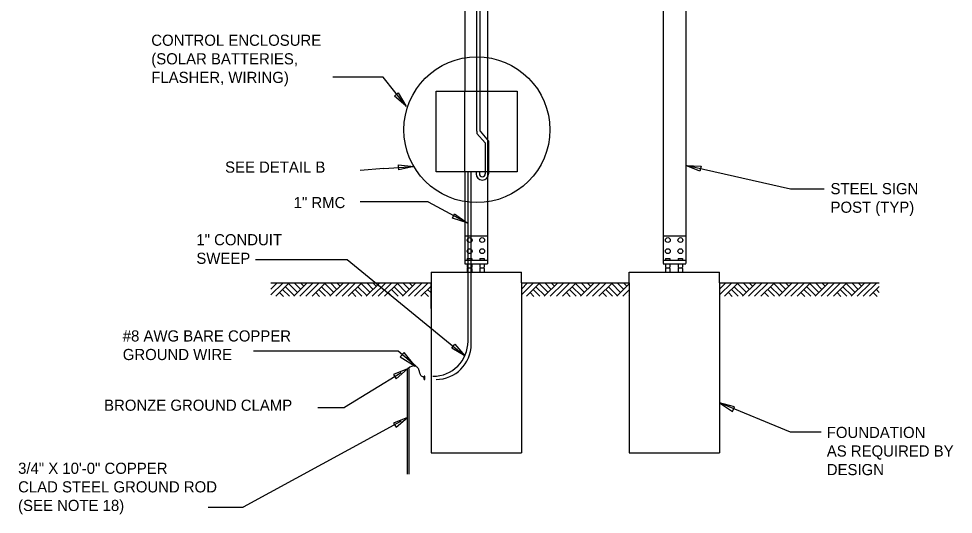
# Model space of a CAD drawing. Extents: x 1299104.6 to 1299141.5, y 239713.3 to 239735.3.
# Drawn here: x 1299119.14 to 1299129.2, y 239723.83 to 239729.17 of the extents above; entities that cross this region are included whole.
import ezdxf

# ---------------------------------------------------------------- set-up
doc = ezdxf.new("R2010")
doc.units = 0
doc.layers.add('DIM TXT', color=7, linetype='Continuous')
doc.layers.add('PTEXT', color=7, linetype='Continuous')

msp = doc.modelspace()

# ---------------------------------------------------------------- linework, layer by layer
at = {"layer": 'DIM TXT'}
for p, q in [((1299123.064, 239728.541), (1299122.522, 239728.541)), ((1299123.314, 239728.224), (1299123.064, 239728.541)), ((1299123.069, 239727.558), (1299122.816, 239727.537)), ((1299123.069, 239727.558), (1299123.392, 239727.579)), ((1299127.446, 239727.334), (1299126.318, 239727.59)), ((1299127.807, 239727.334), (1299127.446, 239727.334)), ((1299123.547, 239727.198), (1299122.816, 239727.198)), ((1299123.547, 239727.198), (1299123.965, 239726.972)), ((1299121.689, 239726.579), (1299122.676, 239726.579)), ((1299122.676, 239726.579), (1299123.941, 239725.54)), ((1299121.854, 239726.196), (1299121.986, 239726.326)), ((1299121.854, 239726.26), (1299121.921, 239726.326)), ((1299121.909, 239726.183), (1299122.053, 239726.326)), ((1299122.1, 239726.182), (1299122.246, 239726.326)), ((1299122.106, 239726.326), (1299122.176, 239726.256)), ((1299122.165, 239726.182), (1299122.311, 239726.326)), ((1299122.174, 239726.326), (1299122.21, 239726.29)), ((1299122.23, 239726.182), (1299122.376, 239726.326)), ((1299122.298, 239726.183), (1299122.443, 239726.326)), ((1299122.49, 239726.182), (1299122.636, 239726.326)), ((1299122.496, 239726.326), (1299122.566, 239726.256)), ((1299122.555, 239726.182), (1299122.701, 239726.326)), ((1299122.563, 239726.326), (1299122.599, 239726.29)), ((1299122.62, 239726.182), (1299122.766, 239726.326)), ((1299122.688, 239726.183), (1299122.833, 239726.326)), ((1299122.88, 239726.182), (1299123.026, 239726.326)), ((1299122.886, 239726.326), (1299122.955, 239726.256)), ((1299122.945, 239726.182), (1299123.091, 239726.326)), ((1299122.953, 239726.326), (1299122.989, 239726.29)), ((1299123.01, 239726.182), (1299123.156, 239726.326)), ((1299123.078, 239726.183), (1299123.223, 239726.326)), ((1299123.27, 239726.182), (1299123.416, 239726.326)), ((1299123.276, 239726.326), (1299123.345, 239726.256)), ((1299123.335, 239726.182), (1299123.481, 239726.326)), ((1299123.343, 239726.326), (1299123.379, 239726.29)), ((1299123.4, 239726.182), (1299123.546, 239726.326)), ((1299124.55, 239726.196), (1299124.682, 239726.326)), ((1299124.55, 239726.26), (1299124.617, 239726.326)), ((1299124.604, 239726.183), (1299124.749, 239726.326)), ((1299124.796, 239726.182), (1299124.942, 239726.326)), ((1299124.802, 239726.326), (1299124.871, 239726.256)), ((1299124.861, 239726.182), (1299125.007, 239726.326)), ((1299124.869, 239726.326), (1299124.905, 239726.29)), ((1299124.926, 239726.182), (1299125.072, 239726.326)), ((1299124.994, 239726.183), (1299125.139, 239726.326)), ((1299125.186, 239726.182), (1299125.332, 239726.326)), ((1299125.192, 239726.326), (1299125.261, 239726.256)), ((1299125.251, 239726.182), (1299125.397, 239726.326)), ((1299125.259, 239726.326), (1299125.295, 239726.29)), ((1299125.316, 239726.182), (1299125.462, 239726.326)), ((1299125.384, 239726.183), (1299125.529, 239726.326)), ((1299125.582, 239726.326), (1299125.651, 239726.256)), ((1299125.649, 239726.326), (1299125.685, 239726.29)), ((1299126.683, 239726.196), (1299126.815, 239726.326)), ((1299126.683, 239726.26), (1299126.75, 239726.326)), ((1299126.737, 239726.183), (1299126.882, 239726.326)), ((1299126.929, 239726.182), (1299127.075, 239726.326)), ((1299126.935, 239726.326), (1299127.005, 239726.256)), ((1299126.994, 239726.182), (1299127.14, 239726.326)), ((1299127.002, 239726.326), (1299127.038, 239726.29)), ((1299127.059, 239726.182), (1299127.205, 239726.326)), ((1299127.127, 239726.183), (1299127.272, 239726.326)), ((1299127.319, 239726.182), (1299127.465, 239726.326)), ((1299127.325, 239726.326), (1299127.394, 239726.256)), ((1299127.384, 239726.182), (1299127.53, 239726.326)), ((1299127.392, 239726.326), (1299127.428, 239726.29)), ((1299127.449, 239726.182), (1299127.595, 239726.326)), ((1299127.517, 239726.183), (1299127.662, 239726.326)), ((1299127.709, 239726.182), (1299127.855, 239726.326)), ((1299127.715, 239726.326), (1299127.784, 239726.256)), ((1299127.774, 239726.182), (1299127.92, 239726.326)), ((1299127.782, 239726.326), (1299127.818, 239726.29)), ((1299127.839, 239726.182), (1299127.985, 239726.326)), ((1299127.907, 239726.183), (1299128.052, 239726.326)), ((1299128.099, 239726.182), (1299128.245, 239726.326)), ((1299128.105, 239726.326), (1299128.174, 239726.256)), ((1299128.164, 239726.182), (1299128.31, 239726.326)), ((1299128.172, 239726.326), (1299128.208, 239726.29)), ((1299128.228, 239726.182), (1299128.375, 239726.326)), ((1299121.981, 239726.255), (1299122.054, 239726.182)), ((1299122.011, 239726.285), (1299122.107, 239726.189)), ((1299122.046, 239726.32), (1299122.142, 239726.223)), ((1299122.371, 239726.255), (1299122.444, 239726.182)), ((1299122.401, 239726.285), (1299122.497, 239726.189)), ((1299122.436, 239726.32), (1299122.532, 239726.223)), ((1299122.761, 239726.255), (1299122.834, 239726.182)), ((1299122.791, 239726.285), (1299122.887, 239726.189)), ((1299122.826, 239726.32), (1299122.922, 239726.223)), ((1299123.151, 239726.255), (1299123.224, 239726.182)), ((1299123.181, 239726.285), (1299123.276, 239726.189)), ((1299123.216, 239726.32), (1299123.312, 239726.223)), ((1299123.468, 239726.183), (1299123.578, 239726.292)), ((1299123.541, 239726.255), (1299123.578, 239726.218)), ((1299123.571, 239726.285), (1299123.578, 239726.278)), ((1299124.677, 239726.255), (1299124.75, 239726.182)), ((1299124.707, 239726.285), (1299124.803, 239726.189)), ((1299124.742, 239726.32), (1299124.838, 239726.223)), ((1299125.067, 239726.255), (1299125.14, 239726.182)), ((1299125.097, 239726.285), (1299125.192, 239726.189)), ((1299125.132, 239726.32), (1299125.228, 239726.223)), ((1299125.457, 239726.255), (1299125.53, 239726.182)), ((1299125.487, 239726.285), (1299125.582, 239726.189)), ((1299125.522, 239726.32), (1299125.618, 239726.223)), ((1299125.576, 239726.182), (1299125.711, 239726.316)), ((1299125.641, 239726.182), (1299125.711, 239726.251)), ((1299126.81, 239726.255), (1299126.883, 239726.182)), ((1299126.84, 239726.285), (1299126.936, 239726.189)), ((1299126.875, 239726.32), (1299126.971, 239726.223)), ((1299127.2, 239726.255), (1299127.273, 239726.182)), ((1299127.23, 239726.285), (1299127.326, 239726.189)), ((1299127.265, 239726.32), (1299127.361, 239726.223)), ((1299127.59, 239726.255), (1299127.663, 239726.182)), ((1299127.62, 239726.285), (1299127.715, 239726.189)), ((1299127.655, 239726.32), (1299127.751, 239726.223)), ((1299127.98, 239726.255), (1299128.052, 239726.182)), ((1299128.01, 239726.285), (1299128.105, 239726.189)), ((1299128.045, 239726.32), (1299128.141, 239726.223)), ((1299128.297, 239726.183), (1299128.401, 239726.286)), ((1299128.37, 239726.255), (1299128.401, 239726.224)), ((1299121.948, 239726.222), (1299121.989, 239726.18)), ((1299122.338, 239726.222), (1299122.379, 239726.18)), ((1299122.728, 239726.222), (1299122.769, 239726.18)), ((1299123.118, 239726.222), (1299123.159, 239726.18)), ((1299123.507, 239726.222), (1299123.549, 239726.18)), ((1299124.644, 239726.222), (1299124.685, 239726.18)), ((1299125.034, 239726.222), (1299125.075, 239726.18)), ((1299125.424, 239726.222), (1299125.465, 239726.18)), ((1299125.706, 239726.182), (1299125.711, 239726.187)), ((1299126.777, 239726.222), (1299126.818, 239726.18)), ((1299127.167, 239726.222), (1299127.208, 239726.18)), ((1299127.557, 239726.222), (1299127.598, 239726.18)), ((1299127.947, 239726.222), (1299127.988, 239726.18)), ((1299128.336, 239726.222), (1299128.378, 239726.18)), ((1299123.225, 239725.592), (1299121.666, 239725.592)), ((1299123.414, 239725.429), (1299123.225, 239725.592)), ((1299123.257, 239725.357), (1299122.648, 239724.986)), ((1299127.447, 239724.719), (1299126.683, 239725.034)), ((1299122.361, 239724.986), (1299122.648, 239724.986)), ((1299123.257, 239724.836), (1299121.556, 239723.91)), ((1299127.774, 239724.719), (1299127.447, 239724.719)), ((1299121.179, 239723.91), (1299121.556, 239723.91))]:
    msp.add_line(p, q, dxfattribs=at)
for points in [[(1299123.184, 239728.338), (1299123.225, 239728.372), (1299123.308, 239728.231)], [(1299123.232, 239727.545), (1299123.229, 239727.599), (1299123.392, 239727.579)], [(1299126.483, 239727.583), (1299126.471, 239727.53), (1299126.318, 239727.59)], [(1299123.808, 239727.022), (1299123.832, 239727.071), (1299123.965, 239726.974)], [(1299123.8, 239725.623), (1299123.834, 239725.665), (1299123.941, 239725.54)], [(1299123.287, 239725.576), (1299123.246, 239725.529), (1299123.407, 239725.431)], [(1299123.174, 239725.338), (1299123.202, 239725.292), (1299123.326, 239725.399)], [(1299126.82, 239724.942), (1299126.842, 239724.992), (1299126.683, 239725.034)], [(1299123.174, 239724.817), (1299123.202, 239724.771), (1299123.326, 239724.878)]]:
    msp.add_lwpolyline(points, close=True, dxfattribs=at)
at = {"layer": 'PTEXT'}
for p, q in [((1299126.318, 239732.225), (1299126.318, 239726.534)), ((1299123.942, 239731.778), (1299123.942, 239728.392)), ((1299124.185, 239730.895), (1299124.185, 239728.392)), ((1299126.075, 239730.947), (1299126.075, 239726.534)), ((1299123.942, 239727.523), (1299123.942, 239728.392)), ((1299124.185, 239728.392), (1299124.185, 239727.523)), ((1299123.942, 239727.523), (1299123.942, 239726.53)), ((1299123.976, 239725.997), (1299123.976, 239727.523)), ((1299124.01, 239725.997), (1299124.01, 239727.523)), ((1299124.062, 239727.523), (1299124.062, 239727.501)), ((1299124.098, 239727.523), (1299124.098, 239727.501)), ((1299124.185, 239727.523), (1299124.185, 239726.53)), ((1299123.942, 239726.832), (1299124.185, 239726.832)), ((1299126.075, 239726.832), (1299126.318, 239726.832)), ((1299123.942, 239726.571), (1299124.185, 239726.571)), ((1299123.942, 239726.53), (1299124.185, 239726.53)), ((1299123.967, 239726.59), (1299124.015, 239726.59)), ((1299123.967, 239726.59), (1299123.967, 239726.571)), ((1299123.967, 239726.53), (1299123.967, 239726.497)), ((1299124.015, 239726.59), (1299124.015, 239726.571)), ((1299124.015, 239726.53), (1299124.015, 239726.497)), ((1299124.104, 239726.59), (1299124.151, 239726.59)), ((1299124.104, 239726.59), (1299124.104, 239726.571)), ((1299124.104, 239726.53), (1299124.104, 239726.497)), ((1299124.151, 239726.59), (1299124.151, 239726.571)), ((1299124.151, 239726.53), (1299124.151, 239726.497)), ((1299126.075, 239726.571), (1299126.318, 239726.571)), ((1299126.075, 239726.53), (1299126.318, 239726.53)), ((1299126.1, 239726.59), (1299126.1, 239726.571)), ((1299126.1, 239726.59), (1299126.148, 239726.59)), ((1299126.1, 239726.53), (1299126.1, 239726.497)), ((1299126.148, 239726.59), (1299126.148, 239726.571)), ((1299126.148, 239726.53), (1299126.148, 239726.497)), ((1299126.237, 239726.59), (1299126.237, 239726.571)), ((1299126.237, 239726.59), (1299126.284, 239726.59)), ((1299126.237, 239726.53), (1299126.237, 239726.497)), ((1299126.284, 239726.59), (1299126.284, 239726.571)), ((1299126.284, 239726.53), (1299126.284, 239726.497)), ((1299123.578, 239726.441), (1299124.55, 239726.441)), ((1299123.578, 239726.441), (1299123.578, 239726.326)), ((1299123.967, 239726.497), (1299123.976, 239726.489)), ((1299123.967, 239726.481), (1299123.976, 239726.489)), ((1299123.967, 239726.481), (1299123.967, 239726.441)), ((1299123.976, 239726.489), (1299124.006, 239726.489)), ((1299124.015, 239726.497), (1299124.006, 239726.489)), ((1299124.015, 239726.481), (1299124.006, 239726.489)), ((1299124.015, 239726.481), (1299124.015, 239726.441)), ((1299124.104, 239726.497), (1299124.113, 239726.489)), ((1299124.104, 239726.481), (1299124.113, 239726.489)), ((1299124.104, 239726.481), (1299124.104, 239726.441)), ((1299124.113, 239726.489), (1299124.142, 239726.489)), ((1299124.151, 239726.497), (1299124.142, 239726.489)), ((1299124.151, 239726.481), (1299124.142, 239726.489)), ((1299124.151, 239726.481), (1299124.151, 239726.441)), ((1299124.55, 239726.326), (1299124.55, 239726.441)), ((1299125.711, 239726.441), (1299126.683, 239726.441)), ((1299125.711, 239726.326), (1299125.711, 239726.441)), ((1299126.1, 239726.497), (1299126.109, 239726.489)), ((1299126.1, 239726.481), (1299126.109, 239726.489)), ((1299126.1, 239726.481), (1299126.1, 239726.441)), ((1299126.109, 239726.489), (1299126.139, 239726.489)), ((1299126.148, 239726.497), (1299126.139, 239726.489)), ((1299126.148, 239726.481), (1299126.139, 239726.489)), ((1299126.148, 239726.481), (1299126.148, 239726.441)), ((1299126.237, 239726.497), (1299126.246, 239726.489)), ((1299126.237, 239726.481), (1299126.246, 239726.489)), ((1299126.237, 239726.481), (1299126.237, 239726.441)), ((1299126.246, 239726.489), (1299126.275, 239726.489)), ((1299126.284, 239726.497), (1299126.275, 239726.489)), ((1299126.284, 239726.481), (1299126.275, 239726.489)), ((1299126.284, 239726.481), (1299126.284, 239726.441)), ((1299126.683, 239726.326), (1299126.683, 239726.441)), ((1299121.854, 239726.326), (1299123.578, 239726.326)), ((1299123.578, 239726.051), (1299123.578, 239726.326)), ((1299123.578, 239726.326), (1299123.578, 239724.498)), ((1299124.55, 239726.326), (1299125.711, 239726.326)), ((1299124.55, 239726.326), (1299124.55, 239724.498)), ((1299125.711, 239726.326), (1299125.711, 239724.498)), ((1299126.683, 239726.326), (1299128.401, 239726.326)), ((1299126.683, 239726.326), (1299126.683, 239724.498)), ((1299123.976, 239725.698), (1299123.976, 239725.997)), ((1299124.01, 239725.665), (1299124.01, 239725.997)), ((1299123.896, 239725.567), (1299123.896, 239725.567)), ((1299123.326, 239724.266), (1299123.326, 239725.403)), ((1299123.341, 239725.403), (1299123.326, 239725.403)), ((1299123.341, 239724.266), (1299123.341, 239725.403)), ((1299123.505, 239725.287), (1299123.505, 239725.32)), ((1299123.512, 239725.287), (1299123.512, 239725.32)), ((1299123.578, 239724.498), (1299124.55, 239724.498)), ((1299125.711, 239724.498), (1299126.683, 239724.498))]:
    msp.add_line(p, q, dxfattribs=at)
for points in [[(1299124.072, 239727.958), (1299124.072, 239730.838)], [(1299124.106, 239727.958), (1299124.106, 239730.838)], [(1299124.072, 239727.958), (1299124.072, 239727.933), (1299124.161, 239727.834), (1299124.161, 239727.501)], [(1299124.106, 239727.958), (1299124.197, 239727.852), (1299124.197, 239727.501)], [(1299123.504, 239725.309), (1299123.503, 239725.309), (1299123.495, 239725.311), (1299123.489, 239725.314), (1299123.483, 239725.317), (1299123.477, 239725.321), (1299123.473, 239725.325), (1299123.469, 239725.33), (1299123.466, 239725.335), (1299123.464, 239725.34), (1299123.461, 239725.346), (1299123.459, 239725.353), (1299123.457, 239725.359), (1299123.455, 239725.366), (1299123.453, 239725.374), (1299123.451, 239725.381), (1299123.448, 239725.388), (1299123.445, 239725.396), (1299123.44, 239725.403), (1299123.436, 239725.41), (1299123.43, 239725.417), (1299123.423, 239725.423), (1299123.415, 239725.428), (1299123.405, 239725.432), (1299123.394, 239725.433), (1299123.382, 239725.431), (1299123.367, 239725.426), (1299123.351, 239725.417), (1299123.333, 239725.403)]]:
    msp.add_lwpolyline(points, dxfattribs=at)
for points in [[(1299123.633, 239727.523), (1299123.633, 239728.392), (1299124.503, 239728.392), (1299124.503, 239727.523)], [(1299123.505, 239725.32), (1299123.505, 239725.287), (1299123.512, 239725.287), (1299123.512, 239725.32)]]:
    msp.add_lwpolyline(points, close=True, dxfattribs=at)
for centre, radius in [((1299124.071, 239727.975), 0.785), ((1299123.993, 239726.787), 0.0261), ((1299124.128, 239726.787), 0.0261), ((1299126.126, 239726.787), 0.0261), ((1299126.261, 239726.787), 0.0261), ((1299123.993, 239726.667), 0.0261), ((1299124.128, 239726.667), 0.0261), ((1299126.126, 239726.667), 0.0261), ((1299126.261, 239726.667), 0.0261)]:
    msp.add_circle(centre, radius, dxfattribs=at)
for centre, radius, start in [((1299124.13, 239727.501), 0.0675, 180), ((1299124.13, 239727.501), 0.0315, 180), ((1299123.598, 239725.698), 0.378, 270), ((1299123.632, 239725.665), 0.378, 270)]:
    msp.add_arc(centre, radius, start, 0, dxfattribs=at)

# ---------------------------------------------------------------- texts
at = {"layer": 'DIM TXT'}
for s, p in [('CONTROL ENCLOSURE ', (1299120.568, 239728.879)), ('(SOLAR BATTERIES, ', (1299120.568, 239728.679)), ('FLASHER, WIRING)', (1299120.568, 239728.479)), ('SEE DETAIL B', (1299121.362, 239727.513)), ('STEEL SIGN ', (1299127.876, 239727.281)), ('1" RMC', (1299122.1, 239727.131)), ('POST (TYP)', (1299127.876, 239727.081)), ('1" CONDUIT ', (1299121.053, 239726.731)), ('SWEEP', (1299121.053, 239726.531)), ('#8 AWG BARE COPPER ', (1299120.261, 239725.695)), ('GROUND WIRE', (1299120.261, 239725.495)), ('BRONZE GROUND CLAMP', (1299120.06, 239724.949)), ('FOUNDATION ', (1299127.836, 239724.656)), ('AS REQUIRED BY ', (1299127.836, 239724.456)), ('3/4" X 10\'-0" COPPER ', (1299119.135, 239724.27)), ('DESIGN', (1299127.836, 239724.256)), ('CLAD STEEL GROUND ROD ', (1299119.135, 239724.07)), ('(SEE NOTE 18)', (1299119.135, 239723.87))]:
    msp.add_text(s, height=0.12, dxfattribs=at).set_placement(p)

doc.saveas('drawing.dxf')
